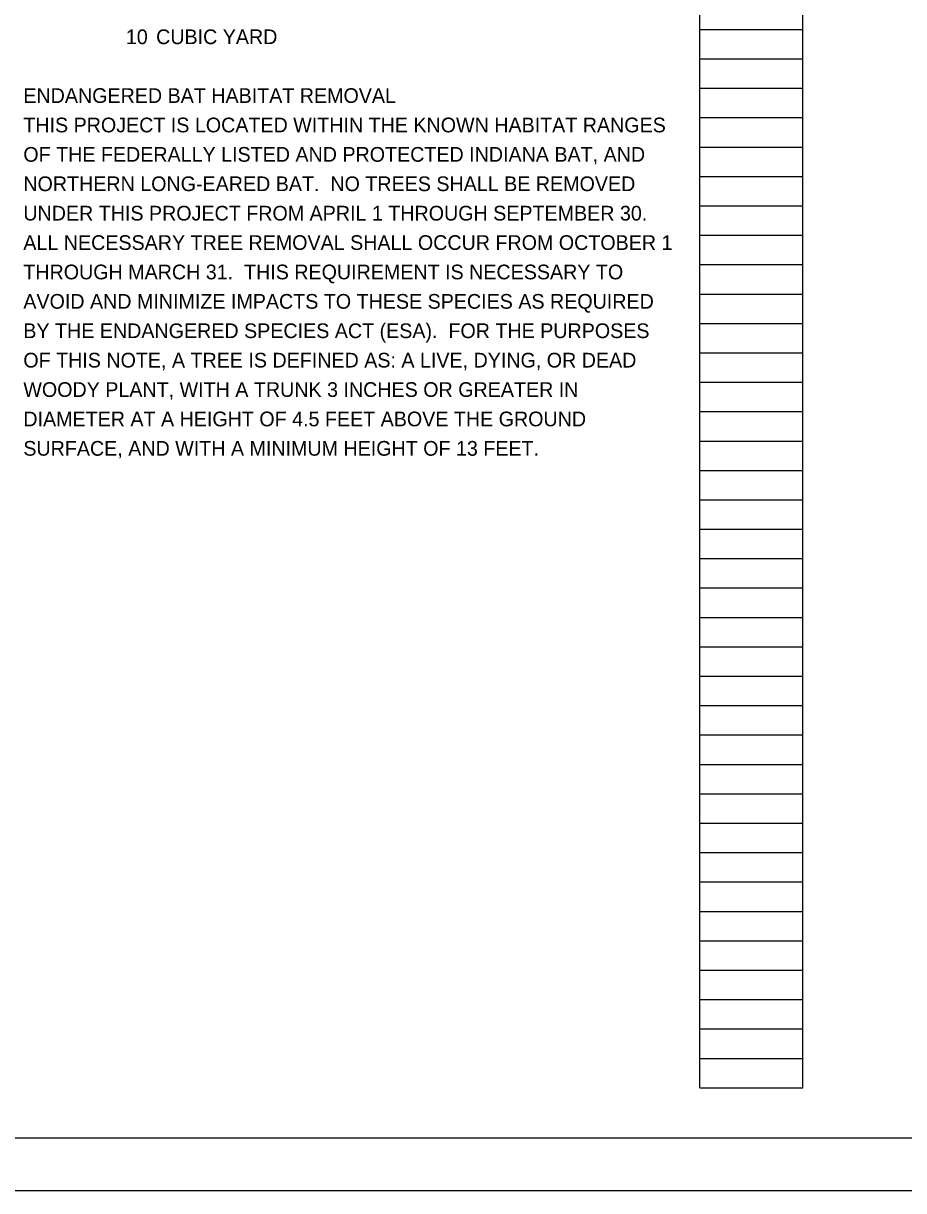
# Model space of a CAD drawing. Extents: x 0 to 34, y 0 to 22.
# Drawn here: x 17.24 to 25.62, y 0 to 11.12 of the extents above; entities that cross this region are included whole.
import ezdxf

# ---------------------------------------------------------------- set-up
doc = ezdxf.new("R2010")
doc.units = 0
for name, color, linetype in [('RD_P_Text', 7, 'Continuous'), ('SC_Scratch1', 7, 'Continuous'), ('SH_Border', 7, 'Continuous'), ('SH_Cut_Line', 7, 'Continuous')]:
    doc.layers.add(name, color=color, linetype=linetype)

msp = doc.modelspace()

# ---------------------------------------------------------------- linework, layer by layer
at = {"layer": 'SC_Scratch1'}
for p, q in [((23.68, 0.98), (23.68, 21.14)), ((24.66, 0.98), (24.66, 21.14)), ((23.68, 11.06), (24.66, 11.06)), ((23.68, 10.78), (24.66, 10.78)), ((23.68, 10.5), (24.66, 10.5)), ((23.68, 10.22), (24.66, 10.22)), ((23.68, 9.94), (24.66, 9.94)), ((23.68, 9.66), (24.66, 9.66)), ((23.68, 9.38), (24.66, 9.38)), ((23.68, 9.1), (24.66, 9.1)), ((23.68, 8.82), (24.66, 8.82)), ((23.68, 8.54), (24.66, 8.54)), ((23.68, 8.26), (24.66, 8.26)), ((23.68, 7.98), (24.66, 7.98)), ((23.68, 7.7), (24.66, 7.7)), ((23.68, 7.42), (24.66, 7.42)), ((23.68, 7.14), (24.66, 7.14)), ((23.68, 6.86), (24.66, 6.86)), ((23.68, 6.58), (24.66, 6.58)), ((23.68, 6.3), (24.66, 6.3)), ((23.68, 6.02), (24.66, 6.02)), ((23.68, 5.74), (24.66, 5.74)), ((23.68, 5.46), (24.66, 5.46)), ((23.68, 5.18), (24.66, 5.18)), ((23.68, 4.9), (24.66, 4.9)), ((23.68, 4.62), (24.66, 4.62)), ((23.68, 4.34), (24.66, 4.34)), ((23.68, 4.06), (24.66, 4.06)), ((23.68, 3.78), (24.66, 3.78)), ((23.68, 3.5), (24.66, 3.5)), ((23.68, 3.22), (24.66, 3.22)), ((23.68, 2.94), (24.66, 2.94)), ((23.68, 2.66), (24.66, 2.66)), ((23.68, 2.38), (24.66, 2.38)), ((23.68, 2.1), (24.66, 2.1)), ((23.68, 1.82), (24.66, 1.82)), ((23.68, 1.54), (24.66, 1.54)), ((23.68, 1.26), (24.66, 1.26)), ((23.68, 0.98), (24.66, 0.98))]:
    msp.add_line(p, q, dxfattribs=at)
at = {"layer": 'SH_Border'}
msp.add_lwpolyline([(1.5, 21.5), (33.5, 21.5), (33.5, 0.5), (1.5, 0.5)], close=True, dxfattribs=at)
at = {"layer": 'SH_Cut_Line'}
msp.add_lwpolyline([(0, 0), (34, 0), (34, 22), (0, 22)], close=True, dxfattribs=at)

# ---------------------------------------------------------------- texts
at = {"layer": 'RD_P_Text'}
for s, p in [('        10', (17.8, 10.92)), (' CUBIC YARD', (18.452, 10.92)), ('ENDANGERED BAT HABITAT REMOVAL', (17.24, 10.36)), ('THIS PROJECT IS LOCATED WITHIN THE KNOWN HABITAT RANGES ', (17.24, 10.08)), ('OF THE FEDERALLY LISTED AND PROTECTED INDIANA BAT, AND ', (17.24, 9.8)), ('NORTHERN LONG-EARED BAT.  NO TREES SHALL BE REMOVED ', (17.24, 9.52)), ('UNDER THIS PROJECT FROM APRIL 1 THROUGH SEPTEMBER 30.  ', (17.24, 9.24)), ('ALL NECESSARY TREE REMOVAL SHALL OCCUR FROM OCTOBER 1 ', (17.24, 8.96)), ('THROUGH MARCH 31.  THIS REQUIREMENT IS NECESSARY TO ', (17.24, 8.68)), ('AVOID AND MINIMIZE IMPACTS TO THESE SPECIES AS REQUIRED ', (17.24, 8.4)), ('BY THE ENDANGERED SPECIES ACT (ESA).  FOR THE PURPOSES ', (17.24, 8.12)), ('OF THIS NOTE, A TREE IS DEFINED AS: A LIVE, DYING, OR DEAD ', (17.24, 7.84)), ('WOODY PLANT, WITH A TRUNK 3 INCHES OR GREATER IN ', (17.24, 7.56)), ('DIAMETER AT A HEIGHT OF 4.5 FEET ABOVE THE GROUND ', (17.24, 7.28)), ('SURFACE, AND WITH A MINIMUM HEIGHT OF 13 FEET.', (17.24, 7))]:
    msp.add_text(s, height=0.14, dxfattribs=at).set_placement(p)

doc.saveas('drawing.dxf')
